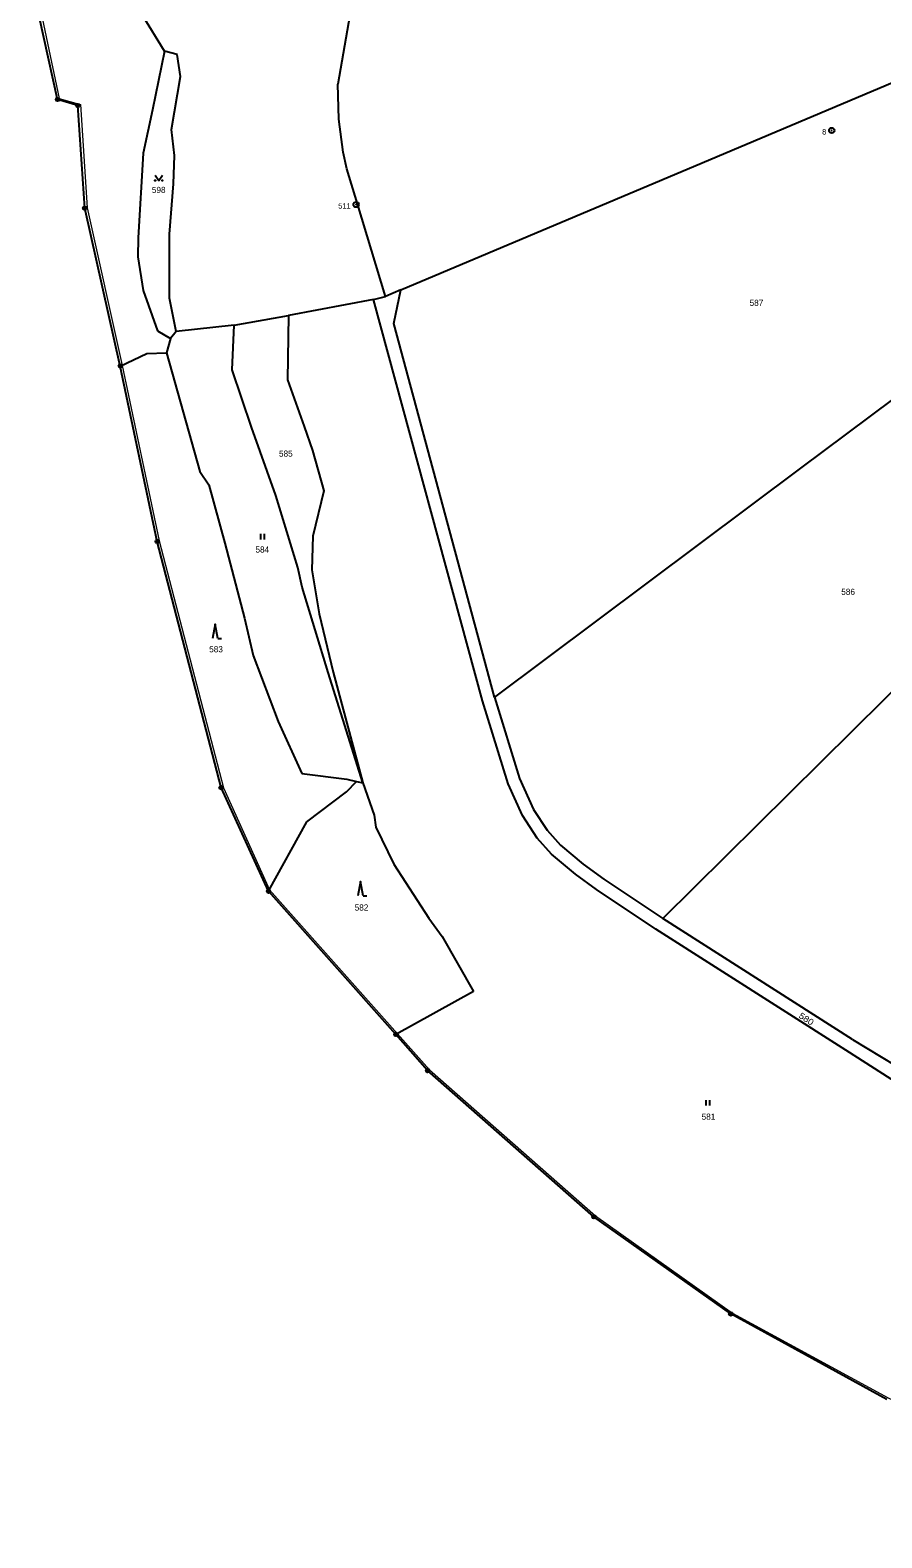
# Model space of a CAD drawing. Extents: x -653193 to -651624, y -1092017 to -1090260.
# Drawn here: x -653078.6 to -652842.7, y -1092015.7 to -1091598.3 of the extents above; entities that cross this region are included whole.
import ezdxf
from ezdxf.enums import TextEntityAlignment as Align

# ---------------------------------------------------------------- set-up
doc = ezdxf.new("R2010")
doc.units = 0
doc.header["$LTSCALE"] = 0.68
for name, color, linetype, lineweight in [('1', 7, 'Continuous', 25), ('3', 7, 'Continuous', 25), ('4', 7, 'Continuous', 13), ('8', 7, 'Continuous', 25)]:
    doc.layers.add(name, color=color, linetype=linetype, lineweight=lineweight)
doc.layers.add('2', color=7, linetype='Continuous')

msp = doc.modelspace()

# ---------------------------------------------------------------- linework, layer by layer
at = {"layer": '1'}
for p, q in [((-653041.4, -1091604.11), (-653047.35, -1091594.38)), ((-652892.48, -1091635), (-652809.38, -1091599.93)), ((-653041.4, -1091604.11), (-653044.69, -1091620.34)), ((-653037.88, -1091605.08), (-653041.4, -1091604.11)), ((-653036.96, -1091611.17), (-653037.88, -1091605.08)), ((-653039.41, -1091625.83), (-653036.96, -1091611.17)), ((-652993.08, -1091622.93), (-652993.35, -1091613.24)), ((-653065.36, -1091619.16), (-653070.97, -1091617.5)), ((-653063.44, -1091647.61), (-653065.36, -1091619.16)), ((-653038.61, -1091632.99), (-653039.41, -1091625.83)), ((-652991.89, -1091632.06), (-652993.08, -1091622.93)), ((-653038.85, -1091640.89), (-653038.61, -1091632.99)), ((-652990.84, -1091636.74), (-652991.89, -1091632.06)), ((-652987.9, -1091646.38), (-652990.84, -1091636.74)), ((-652975.92, -1091670.2), (-652892.48, -1091635)), ((-653039.98, -1091654.79), (-653038.85, -1091640.89)), ((-652980.12, -1091672.08), (-652987.9, -1091646.38)), ((-653053.6, -1091691.29), (-653063.44, -1091647.61)), ((-653039.96, -1091672.52), (-653039.98, -1091654.79)), ((-652776.6, -1091653.24), (-652865.28, -1091719.6)), ((-653048.63, -1091655.76), (-653048.74, -1091661.03)), ((-653048.74, -1091661.03), (-653047.28, -1091670.38)), ((-653047.28, -1091670.38), (-653043.3, -1091681.53)), ((-652983.48, -1091672.89), (-652980.12, -1091672.08)), ((-652975.92, -1091670.2), (-652980.12, -1091672.08)), ((-652977.9, -1091679.48), (-652975.92, -1091670.2)), ((-653038.14, -1091681.76), (-653039.96, -1091672.52)), ((-652983.48, -1091672.89), (-653007.03, -1091677.32)), ((-652953.34, -1091783.97), (-652983.48, -1091672.89)), ((-653022.09, -1091680.01), (-653038.14, -1091681.76)), ((-653022.62, -1091692.34), (-653022.09, -1091680.01)), ((-653022.09, -1091680.01), (-653007.03, -1091677.32)), ((-653007.03, -1091677.32), (-653007.34, -1091695.11)), ((-652949.98, -1091782.99), (-652977.9, -1091679.48)), ((-653043.3, -1091681.53), (-653039.68, -1091683.64)), ((-653039.68, -1091683.64), (-653040.79, -1091687.68)), ((-653038.14, -1091681.76), (-653039.68, -1091683.64)), ((-653053.6, -1091691.29), (-653046.26, -1091687.81)), ((-653046.26, -1091687.81), (-653040.79, -1091687.68)), ((-653040.79, -1091687.68), (-653031.54, -1091720.5)), ((-653043.39, -1091739.84), (-653053.6, -1091691.29)), ((-653017.31, -1091708.23), (-653022.62, -1091692.34)), ((-653007.34, -1091695.11), (-653002.73, -1091708.01)), ((-653010.53, -1091727.15), (-653017.31, -1091708.23)), ((-653002.73, -1091708.01), (-653000.34, -1091714.65)), ((-653000.34, -1091714.65), (-652997.26, -1091725.86)), ((-653031.54, -1091720.5), (-653029.12, -1091724.22)), ((-652865.28, -1091719.6), (-652949.98, -1091782.99)), ((-653029.12, -1091724.22), (-653024.69, -1091740.34)), ((-652997.26, -1091725.86), (-653000.26, -1091738.38)), ((-653004.44, -1091747.05), (-653010.53, -1091727.15)), ((-653000.26, -1091738.38), (-653000.56, -1091747.7)), ((-653025.71, -1091808.01), (-653043.39, -1091739.84)), ((-653024.69, -1091740.34), (-653019.2, -1091761.13)), ((-653003.27, -1091752.47), (-653004.44, -1091747.05)), ((-653000.56, -1091747.7), (-652998.55, -1091759.93)), ((-652996, -1091776.12), (-653003.27, -1091752.47)), ((-653019.2, -1091761.13), (-653016.85, -1091771.47)), ((-652998.55, -1091759.93), (-652994.68, -1091776.08)), ((-652903.41, -1091844.28), (-652823.28, -1091765)), ((-653016.85, -1091771.47), (-653009.87, -1091789.68)), ((-652986.44, -1091806.68), (-652996, -1091776.12)), ((-652994.68, -1091776.08), (-652986.44, -1091806.68)), ((-652946.22, -1091807), (-652953.34, -1091783.97)), ((-652949.98, -1091782.99), (-652943.02, -1091805.51)), ((-653009.87, -1091789.68), (-653003.32, -1091804.05)), ((-653003.32, -1091804.05), (-652990.91, -1091805.64)), ((-652990.91, -1091805.64), (-652988.16, -1091806.27)), ((-652943.02, -1091805.51), (-652939.2, -1091814.03)), ((-653012.56, -1091836.7), (-653025.71, -1091808.01)), ((-653001.96, -1091817.48), (-652990.93, -1091809.14)), ((-652990.93, -1091809.14), (-652988.16, -1091806.27)), ((-652988.16, -1091806.27), (-652986.44, -1091806.68)), ((-652986.44, -1091806.68), (-652983.31, -1091815.6)), ((-652942.27, -1091815.73), (-652946.22, -1091807)), ((-652939.2, -1091814.03), (-652935.36, -1091819.82)), ((-653012.56, -1091836.7), (-653001.96, -1091817.48)), ((-652983.31, -1091815.6), (-652982.86, -1091818.96)), ((-652938.14, -1091821.96), (-652942.27, -1091815.73)), ((-652982.86, -1091818.96), (-652977.86, -1091829.23)), ((-652934.16, -1091826.45), (-652938.14, -1091821.96)), ((-652935.36, -1091819.82), (-652931.72, -1091823.93)), ((-652927.57, -1091831.93), (-652934.16, -1091826.45)), ((-652931.72, -1091823.93), (-652925.42, -1091829.17)), ((-652977.86, -1091829.23), (-652968.15, -1091844.19)), ((-652925.42, -1091829.17), (-652919.71, -1091833.33)), ((-652921.72, -1091836.2), (-652927.57, -1091831.93)), ((-652919.71, -1091833.33), (-652903.41, -1091844.28)), ((-652977.28, -1091876.33), (-653012.56, -1091836.7)), ((-652905.32, -1091847.21), (-652921.72, -1091836.2)), ((-652968.15, -1091844.19), (-652964.45, -1091849.22)), ((-652852.73, -1091880.67), (-652905.32, -1091847.21)), ((-652850.84, -1091877.72), (-652903.41, -1091844.28)), ((-652964.45, -1091849.22), (-652955.8, -1091864.48)), ((-652955.8, -1091864.48), (-652977.28, -1091876.33)), ((-652968.5, -1091886.34), (-652977.28, -1091876.33)), ((-652822.22, -1091900.29), (-652852.73, -1091880.67)), ((-652850.84, -1091877.72), (-652838.95, -1091884.94)), ((-652922.45, -1091926.82), (-652968.5, -1091886.34))]:
    msp.add_line(p, q, dxfattribs=at)
for points in [[(-652843.58, -1091523.54), (-652987.13, -1091577.09), (-652993.35, -1091613.24)], [(-653070.97, -1091617.5), (-653078.57, -1091583.12), (-653077.29, -1091581.98)], [(-653044.69, -1091620.34), (-653047.29, -1091632.37), (-653048.63, -1091655.76)], [(-652841.35, -1091977.39), (-652884.55, -1091953.7), (-652922.45, -1091926.82)]]:
    msp.add_lwpolyline(points, dxfattribs=at)
at = {"layer": '3'}
for p, q in [((-653014.711, -1091739.28), (-653014.711, -1091737.78)), ((-653013.71, -1091739.28), (-653013.71, -1091737.78)), ((-653026.61, -1091766.72), (-653025.614, -1091766.72)), ((-652986.35, -1091837.97), (-652985.354, -1091837.97)), ((-652891.391, -1091896.05), (-652891.391, -1091894.55)), ((-652890.39, -1091896.05), (-652890.39, -1091894.55))]:
    msp.add_line(p, q, dxfattribs=at)
for points in [[(-653043.96, -1091638.409), (-653042.96, -1091639.91), (-653041.96, -1091638.409)], [(-653026.61, -1091766.72), (-653027.36, -1091762.72), (-653028.11, -1091766.72)], [(-652986.35, -1091837.97), (-652987.1, -1091833.97), (-652987.85, -1091837.97)]]:
    msp.add_lwpolyline(points, dxfattribs=at)
for centre in [(-653043.96, -1091639.9095), (-653041.96, -1091639.9095)]:
    msp.add_circle(centre, 0.1, dxfattribs=at)
at = {"layer": '4'}
msp.add_lwpolyline([(-653077.75, -1091583), (-653070.49, -1091617.25), (-653064.62, -1091618.93), (-653062.8, -1091647.54), (-653053.06, -1091691.15), (-653042.85, -1091739.69), (-653024.99, -1091808.05), (-653012.25, -1091836.33), (-652976.82, -1091876.16), (-652967.99, -1091886.1), (-652922.02, -1091926.56), (-652884.11, -1091953.46), (-652840.95, -1091976.96), (-652785.14, -1092003.14), (-652778.84, -1092006), (-652758.36, -1092015.7), (-652726.85, -1091990.62), (-652727, -1091987.85), (-652722.65, -1091987.61), (-652684.79, -1091970.22), (-652604.59, -1092002.09)], dxfattribs=at)
at = {"layer": '8'}
for centre, radius in [((-653070.97, -1091617.4999), 0.5), ((-653070.97, -1091617.4999), 0.0303), ((-653065.36, -1091619.1599), 0.5), ((-653065.36, -1091619.1599), 0.0303), ((-652856.6, -1091626.0798), 0.75), ((-652856.6, -1091626.0798), 0.03), ((-653063.44, -1091647.6099), 0.5), ((-652988.29, -1091646.5898), 0.75), ((-652988.29, -1091646.5898), 0.03), ((-653063.44, -1091647.6099), 0.0303), ((-653053.6, -1091691.2899), 0.5), ((-653053.6, -1091691.2899), 0.0303), ((-653043.39, -1091739.8399), 0.5), ((-653043.39, -1091739.8399), 0.0303), ((-653025.71, -1091808.0099), 0.5), ((-653025.71, -1091808.0099), 0.0303), ((-653012.56, -1091836.6999), 0.5), ((-653012.56, -1091836.6999), 0.0303), ((-652977.28, -1091876.3299), 0.5), ((-652977.28, -1091876.3299), 0.0303), ((-652968.5, -1091886.3399), 0.5), ((-652968.5, -1091886.3399), 0.0303), ((-652922.45, -1091926.8199), 0.5), ((-652922.45, -1091926.8199), 0.0303), ((-652884.55, -1091953.6999), 0.5), ((-652884.55, -1091953.6999), 0.0303)]:
    msp.add_circle(centre, radius, dxfattribs=at)

# ---------------------------------------------------------------- texts
at = {"layer": '2'}
for s, p in [('598', (-653042.969, -1091643.385)), ('587', (-652877.439, -1091674.645)), ('585', (-653007.769, -1091716.385)), ('584', (-653014.279, -1091742.935)), ('586', (-652852.059, -1091754.645)), ('583', (-653027.089, -1091770.545)), ('582', (-652986.809, -1091842.045)), ('581', (-652890.729, -1091899.945))]:
    msp.add_text(s, height=1.7, dxfattribs=at).set_placement(p, align=Align.CENTER)
at = {"layer": '2', "width": 1.15}
msp.add_text('580', height=1.7, rotation=327, dxfattribs=at).set_placement((-652864.0854, -1091872.7589), align=Align.CENTER)
at = {"layer": '8'}
for s, p in [('8', (-652858.1, -1091627.197)), ('511', (-652989.789, -1091647.707))]:
    msp.add_text(s, height=1.5, dxfattribs=at).set_placement(p, align=Align.RIGHT)

doc.saveas('drawing.dxf')
